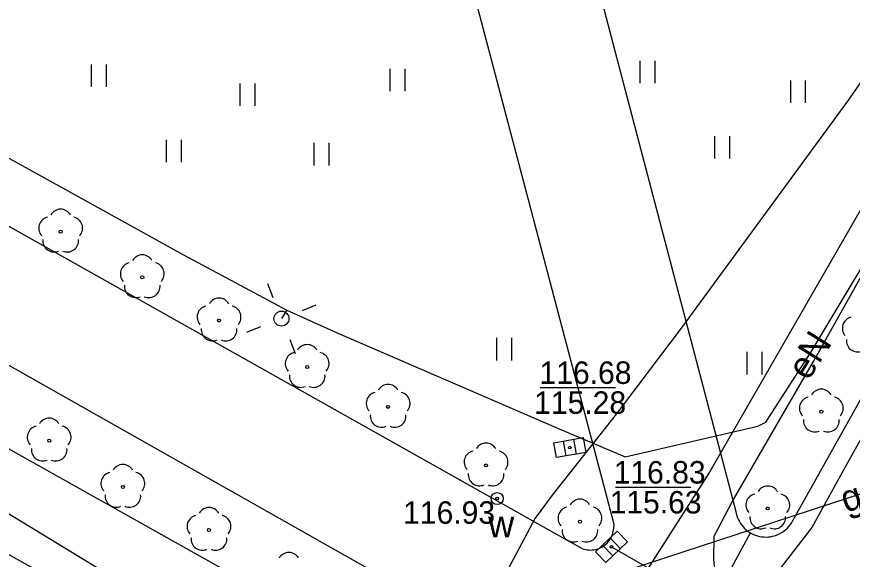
# Model space of a CAD drawing. Extents: x 6434771 to 6436222, y 5663454 to 5664782.
# Drawn here: x 6435389.91 to 6435417.79, y 5663841.05 to 5663859.17 of the extents above; entities that cross this region are included whole.
import ezdxf

# ---------------------------------------------------------------- set-up
doc = ezdxf.new("R2010")
doc.units = 0
for name, color, linetype in [('Warstwa 10', 7, 'Continuous'), ('Warstwa 11', 7, 'Continuous'), ('Warstwa 12', 7, 'Continuous'), ('Warstwa 13', 7, 'Continuous'), ('Warstwa 14', 7, 'Continuous'), ('Warstwa 2', 7, 'Continuous'), ('Warstwa 4', 7, 'Continuous'), ('Warstwa 5', 7, 'Continuous'), ('Warstwa 6', 7, 'Continuous'), ('Warstwa 7', 7, 'Continuous'), ('Warstwa 8', 7, 'Continuous')]:
    doc.layers.add(name, color=color, linetype=linetype)

msp = doc.modelspace()

# ---------------------------------------------------------------- linework, layer by layer
at = {"layer": 'Warstwa 10'}
for points in [[(6435463.66, 5663935.12), (6435460.91, 5663924.89), (6435462.44, 5663921.82), (6435441.07, 5663889.25), (6435439.33, 5663885.38), (6435437.4, 5663886.34), (6435413.02, 5663843.96), (6435405.83, 5663832.69), (6435402.55, 5663834.24), (6435396.16, 5663837.88), (6435373.33, 5663794.86)], [(6435335.178, 5663890.938), (6435338.107, 5663876.762), (6435339.024, 5663872.265), (6435340.015, 5663871.796), (6435342.311, 5663870.369), (6435348.64, 5663866.658), (6435357.869, 5663861.307), (6435368.081, 5663855.303), (6435372.357, 5663852.748), (6435378.044, 5663849.395), (6435386.974, 5663844.189), (6435394.104, 5663839.85), (6435398.635, 5663837.219), (6435400.345, 5663836.282), (6435405.663, 5663833.365), (6435414.229, 5663828.613), (6435413.94, 5663822.627), (6435413.836, 5663820.771), (6435413.916, 5663820.663), (6435415.865, 5663819.454), (6435420.004, 5663817.009), (6435420.232, 5663816.158), (6435417.642, 5663813.363)]]:
    msp.add_lwpolyline(points, dxfattribs=at)
at = {"layer": 'Warstwa 11'}
for centre in [(6435391.373, 5663851.992), (6435394.096, 5663850.467), (6435396.658, 5663849.023), (6435399.599, 5663847.471), (6435402.3, 5663846.14), (6435416.753, 5663845.981), (6435390.99, 5663845.012), (6435405.567, 5663844.183), (6435393.449, 5663843.466), (6435414.966, 5663842.748), (6435408.699, 5663842.307), (6435396.322, 5663842.03)]:
    msp.add_circle(centre, 0.05, dxfattribs=at)
for centre, start, end in [((6435391.373, 5663852.367), 30.1471, 149.8529), ((6435391.016, 5663852.108), 102.1471, 221.8529), ((6435391.73, 5663852.108), 318.1471, 77.8529), ((6435391.153, 5663851.689), 174.1471, 293.8529), ((6435391.593, 5663851.689), 246.1471, 5.8529), ((6435394.096, 5663850.842), 30.1471, 149.8529), ((6435393.739, 5663850.583), 102.1471, 221.8529), ((6435394.453, 5663850.583), 318.1471, 77.8529), ((6435393.876, 5663850.164), 174.1471, 293.8529), ((6435394.316, 5663850.164), 246.1471, 5.8529), ((6435396.658, 5663849.398), 30.1471, 149.8529), ((6435396.301, 5663849.139), 102.1471, 221.8529), ((6435397.015, 5663849.139), 318.1471, 77.8529), ((6435417.829, 5663848.77), 102.1471, 221.8529), ((6435396.438, 5663848.72), 174.1471, 293.8529), ((6435396.878, 5663848.72), 246.1471, 5.8529), ((6435399.599, 5663847.846), 30.1471, 149.8529), ((6435417.966, 5663848.351), 174.1471, 293.8529), ((6435399.242, 5663847.587), 102.1471, 221.8529), ((6435399.956, 5663847.587), 318.1471, 77.8529), ((6435399.379, 5663847.168), 174.1471, 293.8529), ((6435399.819, 5663847.168), 246.1471, 5.8529), ((6435402.3, 5663846.515), 30.1471, 149.8529), ((6435416.753, 5663846.356), 30.1471, 149.8529), ((6435401.943, 5663846.256), 102.1471, 221.8529), ((6435402.657, 5663846.256), 318.1471, 77.8529), ((6435416.396, 5663846.097), 102.1471, 221.8529), ((6435417.11, 5663846.097), 318.1471, 77.8529), ((6435390.99, 5663845.387), 30.1471, 149.8529), ((6435402.08, 5663845.837), 174.1471, 293.8529), ((6435402.52, 5663845.837), 246.1471, 5.8529), ((6435416.533, 5663845.678), 174.1471, 293.8529), ((6435416.973, 5663845.678), 246.1471, 5.8529), ((6435390.633, 5663845.128), 102.1471, 221.8529), ((6435391.347, 5663845.128), 318.1471, 77.8529), ((6435405.567, 5663844.558), 30.1471, 149.8529), ((6435390.77, 5663844.709), 174.1471, 293.8529), ((6435391.21, 5663844.709), 246.1471, 5.8529), ((6435405.21, 5663844.299), 102.1471, 221.8529), ((6435405.924, 5663844.299), 318.1471, 77.8529), ((6435393.449, 5663843.841), 30.1471, 149.8529), ((6435393.092, 5663843.582), 102.1471, 221.8529), ((6435393.806, 5663843.582), 318.1471, 77.8529), ((6435405.347, 5663843.88), 174.1471, 293.8529), ((6435405.787, 5663843.88), 246.1471, 5.8529), ((6435414.966, 5663843.123), 30.1471, 149.8529), ((6435393.229, 5663843.163), 174.1471, 293.8529), ((6435393.669, 5663843.163), 246.1471, 5.8529), ((6435414.609, 5663842.864), 102.1471, 221.8529), ((6435415.323, 5663842.864), 318.1471, 77.8529), ((6435408.699, 5663842.682), 30.1471, 149.8529), ((6435396.322, 5663842.405), 30.1471, 149.8529), ((6435408.342, 5663842.423), 102.1471, 221.8529), ((6435409.056, 5663842.423), 318.1471, 77.8529), ((6435395.965, 5663842.146), 102.1471, 221.8529), ((6435396.679, 5663842.146), 318.1471, 77.8529), ((6435414.746, 5663842.445), 174.1471, 293.8529), ((6435415.186, 5663842.445), 246.1471, 5.8529), ((6435408.479, 5663842.004), 174.1471, 293.8529), ((6435408.919, 5663842.004), 246.1471, 5.8529), ((6435396.102, 5663841.727), 174.1471, 293.8529), ((6435396.542, 5663841.727), 246.1471, 5.8529), ((6435398.987, 5663840.902), 30.1471, 149.8529)]:
    msp.add_arc(centre, 0.375, start, end, dxfattribs=at)
at = {"layer": 'Warstwa 12'}
for points in [[(6435397.393, 5663818.634), (6435398.405, 5663820.277), (6435406.531, 5663834.152), (6435410.27, 5663840.689), (6435424.375, 5663845.312), (6435429.384, 5663846.962), (6435433.786, 5663848.481), (6435435.161, 5663850.8), (6435441.745, 5663862.426), (6435445.915, 5663869.907), (6435449.367, 5663875.506), (6435454.395, 5663883.869), (6435458.364, 5663890.579), (6435460.329, 5663894.152), (6435463.858, 5663901.034), (6435468.538, 5663910.285), (6435471.476, 5663916.034), (6435475.414, 5663922.553), (6435478.498, 5663927.854), (6435482.409, 5663934.511), (6435486.541, 5663941.544)], [(6435447.062, 5663897.437), (6435443.056, 5663889.484), (6435440.358, 5663884.774), (6435435.725, 5663876.52), (6435427.878, 5663862.597), (6435426.954, 5663861.084), (6435424.544, 5663856.758), (6435421.398, 5663851.004), (6435417.624, 5663844.276), (6435416.437, 5663842.113), (6435414.485, 5663839.596), (6435412.652, 5663837.31), (6435409.926, 5663833.859), (6435408.748, 5663832.349), (6435406.751, 5663829.143), (6435405.207, 5663826.749), (6435403.608, 5663824.07), (6435401.471, 5663820.734)], [(6435441.334, 5663891.172), (6435440.258, 5663890.739), (6435440.059, 5663890.088), (6435438.9, 5663888.38), (6435435.762, 5663883.429), (6435427.511, 5663870.737), (6435422.658, 5663863.563), (6435417.63, 5663856.346), (6435412.108, 5663848.819), (6435409.908, 5663845.901), (6435407.773, 5663843.191), (6435407.208, 5663842.42), (6435406.1, 5663840.35), (6435403.6, 5663835.547), (6435399.205, 5663827.094), (6435396.22, 5663821.213), (6435395.68, 5663820.22), (6435394.576, 5663820.761), (6435385.104, 5663826.398), (6435376.487, 5663831.524), (6435367.816, 5663836.677), (6435362.451, 5663839.79), (6435354.317, 5663844.248)], [(6435432.954, 5663828.262), (6435430.584, 5663829.707), (6435425.511, 5663832.518), (6435418.442, 5663836.509), (6435414.692, 5663838.526), (6435414.003, 5663838.98), (6435413.541, 5663839.707), (6435413.243, 5663840.405), (6435413.168, 5663841.045), (6435413.178, 5663841.822), (6435413.773, 5663842.972), (6435416.493, 5663847.66), (6435422.304, 5663858.046), (6435429.673, 5663871.325), (6435437.807, 5663885.787), (6435441.334, 5663891.172)], [(6435371.655, 5663864.561), (6435374.135, 5663863.935), (6435374.75, 5663863.584), (6435375.093, 5663863.414), (6435375.656, 5663863.366), (6435376.838, 5663863.076), (6435377.353, 5663862.408), (6435378.722, 5663860.614), (6435381.246, 5663859.181), (6435383.311, 5663857.888), (6435387.683, 5663855.526), (6435395.472, 5663851.22), (6435398.917, 5663849.374), (6435400.602, 5663848.61), (6435407.924, 5663845.437), (6435410.212, 5663844.473), (6435414.638, 5663845.493), (6435414.902, 5663845.627), (6435416.417, 5663847.98), (6435421.025, 5663855.686)], [(6435398.917, 5663849.374), (6435398.739, 5663849.087)]]:
    msp.add_lwpolyline(points, dxfattribs=at)
at = {"layer": 'Warstwa 14'}
for p, q in [((6435407.372, 5663846.783), (6435409.89, 5663846.783)), ((6435409.887, 5663843.455), (6435412.4, 5663843.455))]:
    msp.add_line(p, q, dxfattribs=at)
for centre in [(6435408.36, 5663844.78), (6435409.748, 5663841.465)]:
    msp.add_circle(centre, 0.045, dxfattribs=at)
at = {"layer": 'Warstwa 2'}
msp.add_circle((6435398.739, 5663849.087), 0.25, dxfattribs=at)
at = {"layer": 'Warstwa 4'}
for p, q in [((6435408.488, 5663845.057), (6435408.576, 5663844.565)), ((6435408.144, 5663844.995), (6435408.232, 5663844.503)), ((6435409.702, 5663841.767), (6435410.047, 5663841.405)), ((6435409.449, 5663841.525), (6435409.794, 5663841.163))]:
    msp.add_line(p, q, dxfattribs=at)
for points in [[(6435398.464, 5663849.785), (6435398.28, 5663850.25)], [(6435399.437, 5663849.362), (6435399.902, 5663849.546)], [(6435398.041, 5663848.812), (6435397.576, 5663848.628)], [(6435399.014, 5663848.389), (6435399.198, 5663847.924)]]:
    msp.add_lwpolyline(points, dxfattribs=at)
for points in [[(6435407.824, 5663844.939), (6435408.808, 5663845.114), (6435408.896, 5663844.621), (6435407.912, 5663844.446)], [(6435409.214, 5663841.301), (6435409.938, 5663841.991), (6435410.282, 5663841.629), (6435409.558, 5663840.939)]]:
    msp.add_lwpolyline(points, close=True, dxfattribs=at)
msp.add_circle((6435405.937, 5663843.08), 0.2, dxfattribs=at)
at = {"layer": 'Warstwa 5'}
for p, q in [((6435415.789, 5663842.322), (6435442.58, 5663890.242)), ((6435406.321, 5663871.508), (6435413.903, 5663842.645)), ((6435402.186, 5663871.198), (6435409.808, 5663842.314)), ((6435362.09, 5663867.682), (6435408.171, 5663841.744)), ((6435356.354, 5663859.8), (6435403.411, 5663833.521)), ((6435410.708, 5663856.951), (6435410.708, 5663857.701)), ((6435411.208, 5663856.951), (6435411.208, 5663857.701)), ((6435392.407, 5663856.827), (6435392.407, 5663857.577)), ((6435392.907, 5663856.827), (6435392.907, 5663857.577)), ((6435402.369, 5663856.684), (6435402.369, 5663857.434)), ((6435402.869, 5663856.684), (6435402.869, 5663857.434)), ((6435415.73, 5663856.294), (6435415.73, 5663857.044)), ((6435416.23, 5663856.294), (6435416.23, 5663857.044)), ((6435397.361, 5663856.194), (6435397.361, 5663856.944)), ((6435397.861, 5663856.194), (6435397.861, 5663856.944)), ((6435413.203, 5663854.437), (6435413.203, 5663855.187)), ((6435413.703, 5663854.437), (6435413.703, 5663855.187)), ((6435394.901, 5663854.313), (6435394.901, 5663855.063)), ((6435395.401, 5663854.313), (6435395.401, 5663855.063)), ((6435399.836, 5663854.207), (6435399.836, 5663854.957)), ((6435400.336, 5663854.207), (6435400.336, 5663854.957)), ((6435405.922, 5663847.695), (6435405.922, 5663848.445)), ((6435406.422, 5663847.695), (6435406.422, 5663848.445)), ((6435414.277, 5663847.226), (6435414.277, 5663847.976)), ((6435414.777, 5663847.226), (6435414.777, 5663847.976)), ((6435413.903, 5663842.645), (6435413.917, 5663842.575)), ((6435413.917, 5663842.575), (6435413.936, 5663842.505)), ((6435409.808, 5663842.314), (6435409.819, 5663842.259)), ((6435409.819, 5663842.259), (6435409.825, 5663842.204)), ((6435413.936, 5663842.505), (6435413.959, 5663842.438)), ((6435413.959, 5663842.438), (6435413.988, 5663842.372)), ((6435413.988, 5663842.372), (6435414.021, 5663842.308)), ((6435414.021, 5663842.308), (6435414.058, 5663842.247)), ((6435415.712, 5663842.201), (6435415.753, 5663842.26)), ((6435415.753, 5663842.26), (6435415.789, 5663842.322)), ((6435409.798, 5663841.927), (6435409.812, 5663841.981)), ((6435409.812, 5663841.981), (6435409.821, 5663842.036)), ((6435409.821, 5663842.036), (6435409.826, 5663842.092)), ((6435409.825, 5663842.204), (6435409.828, 5663842.148)), ((6435409.826, 5663842.092), (6435409.828, 5663842.148)), ((6435414.058, 5663842.247), (6435414.1, 5663842.188)), ((6435414.1, 5663842.188), (6435414.145, 5663842.133)), ((6435414.145, 5663842.133), (6435414.195, 5663842.081)), ((6435414.195, 5663842.081), (6435414.248, 5663842.032)), ((6435414.248, 5663842.032), (6435414.304, 5663841.988)), ((6435414.304, 5663841.988), (6435414.364, 5663841.948)), ((6435415.452, 5663841.956), (6435415.511, 5663841.998)), ((6435415.511, 5663841.998), (6435415.566, 5663842.043)), ((6435415.566, 5663842.043), (6435415.619, 5663842.092)), ((6435415.619, 5663842.092), (6435415.667, 5663842.145)), ((6435415.667, 5663842.145), (6435415.712, 5663842.201)), ((6435408.171, 5663841.744), (6435408.777, 5663841.407)), ((6435409.676, 5663841.677), (6435409.707, 5663841.723)), ((6435409.707, 5663841.723), (6435409.736, 5663841.772)), ((6435409.736, 5663841.772), (6435409.76, 5663841.822)), ((6435409.76, 5663841.822), (6435409.781, 5663841.874)), ((6435409.781, 5663841.874), (6435409.798, 5663841.927)), ((6435414.364, 5663841.948), (6435414.395, 5663841.93)), ((6435414.395, 5663841.93), (6435414.426, 5663841.912)), ((6435414.426, 5663841.912), (6435414.491, 5663841.88)), ((6435414.491, 5663841.88), (6435414.557, 5663841.853)), ((6435414.557, 5663841.853), (6435414.625, 5663841.831)), ((6435414.625, 5663841.831), (6435414.695, 5663841.814)), ((6435414.695, 5663841.814), (6435414.766, 5663841.802)), ((6435414.766, 5663841.802), (6435414.837, 5663841.795)), ((6435414.837, 5663841.795), (6435414.909, 5663841.793)), ((6435414.909, 5663841.793), (6435414.981, 5663841.796)), ((6435414.981, 5663841.796), (6435415.052, 5663841.804)), ((6435415.052, 5663841.804), (6435415.123, 5663841.818)), ((6435415.123, 5663841.818), (6435415.192, 5663841.836)), ((6435415.192, 5663841.836), (6435415.26, 5663841.859)), ((6435415.26, 5663841.859), (6435415.326, 5663841.887)), ((6435415.326, 5663841.887), (6435415.39, 5663841.919)), ((6435415.39, 5663841.919), (6435415.452, 5663841.956)), ((6435409.325, 5663841.41), (6435409.376, 5663841.432)), ((6435409.376, 5663841.432), (6435409.426, 5663841.457)), ((6435409.426, 5663841.457), (6435409.474, 5663841.486)), ((6435409.474, 5663841.486), (6435409.52, 5663841.518)), ((6435409.52, 5663841.518), (6435409.563, 5663841.554)), ((6435409.563, 5663841.554), (6435409.603, 5663841.592)), ((6435409.603, 5663841.592), (6435409.641, 5663841.633)), ((6435409.641, 5663841.633), (6435409.676, 5663841.677)), ((6435408.777, 5663841.407), (6435408.83, 5663841.39)), ((6435408.83, 5663841.39), (6435408.885, 5663841.376)), ((6435408.885, 5663841.376), (6435408.94, 5663841.366)), ((6435408.94, 5663841.366), (6435408.995, 5663841.361)), ((6435408.995, 5663841.361), (6435409.051, 5663841.359)), ((6435409.051, 5663841.359), (6435409.107, 5663841.361)), ((6435409.107, 5663841.361), (6435409.163, 5663841.368)), ((6435409.163, 5663841.368), (6435409.218, 5663841.378)), ((6435409.218, 5663841.378), (6435409.272, 5663841.392)), ((6435409.272, 5663841.392), (6435409.325, 5663841.41))]:
    msp.add_line(p, q, dxfattribs=at)
at = {"layer": 'Warstwa 6'}
for centre in [(6435408.36, 5663844.78), (6435405.937, 5663843.08), (6435409.748, 5663841.465)]:
    msp.add_circle(centre, 0.045, dxfattribs=at)
at = {"layer": 'Warstwa 7'}
msp.add_lwpolyline([(6435409.748, 5663841.465), (6435419.602, 5663835.801)], dxfattribs=at)
at = {"layer": 'Warstwa 8'}
for p, q in [((6435415.789, 5663842.322), (6435442.58, 5663890.242)), ((6435406.321, 5663871.508), (6435413.903, 5663842.645)), ((6435402.186, 5663871.198), (6435409.808, 5663842.314)), ((6435362.09, 5663867.682), (6435408.171, 5663841.744)), ((6435360.367, 5663864.122), (6435406.416, 5663838.025)), ((6435359.318, 5663861.735), (6435404.735, 5663836.275)), ((6435356.354, 5663859.8), (6435403.411, 5663833.521)), ((6435413.903, 5663842.645), (6435413.917, 5663842.575)), ((6435413.917, 5663842.575), (6435413.936, 5663842.505)), ((6435409.808, 5663842.314), (6435409.819, 5663842.259)), ((6435409.819, 5663842.259), (6435409.825, 5663842.204)), ((6435413.936, 5663842.505), (6435413.959, 5663842.438)), ((6435413.959, 5663842.438), (6435413.988, 5663842.372)), ((6435413.988, 5663842.372), (6435414.021, 5663842.308)), ((6435414.021, 5663842.308), (6435414.058, 5663842.247)), ((6435415.712, 5663842.201), (6435415.753, 5663842.26)), ((6435415.753, 5663842.26), (6435415.789, 5663842.322)), ((6435409.798, 5663841.927), (6435409.812, 5663841.981)), ((6435409.812, 5663841.981), (6435409.821, 5663842.036)), ((6435409.821, 5663842.036), (6435409.826, 5663842.092)), ((6435409.825, 5663842.204), (6435409.828, 5663842.148)), ((6435409.826, 5663842.092), (6435409.828, 5663842.148)), ((6435414.058, 5663842.247), (6435414.1, 5663842.188)), ((6435414.1, 5663842.188), (6435414.145, 5663842.133)), ((6435414.145, 5663842.133), (6435414.195, 5663842.081)), ((6435414.195, 5663842.081), (6435414.248, 5663842.032)), ((6435414.248, 5663842.032), (6435414.304, 5663841.988)), ((6435414.304, 5663841.988), (6435414.364, 5663841.948)), ((6435415.452, 5663841.956), (6435415.511, 5663841.998)), ((6435415.511, 5663841.998), (6435415.566, 5663842.043)), ((6435415.566, 5663842.043), (6435415.619, 5663842.092)), ((6435415.619, 5663842.092), (6435415.667, 5663842.145)), ((6435415.667, 5663842.145), (6435415.712, 5663842.201)), ((6435408.171, 5663841.744), (6435408.777, 5663841.407)), ((6435408.603, 5663831.392), (6435414.395, 5663841.93)), ((6435408.603, 5663831.392), (6435414.395, 5663841.93)), ((6435409.676, 5663841.677), (6435409.707, 5663841.723)), ((6435409.707, 5663841.723), (6435409.736, 5663841.772)), ((6435409.736, 5663841.772), (6435409.76, 5663841.822)), ((6435409.76, 5663841.822), (6435409.781, 5663841.874)), ((6435409.781, 5663841.874), (6435409.798, 5663841.927)), ((6435414.364, 5663841.948), (6435414.395, 5663841.93)), ((6435414.395, 5663841.93), (6435414.426, 5663841.912)), ((6435414.426, 5663841.912), (6435414.491, 5663841.88)), ((6435414.491, 5663841.88), (6435414.557, 5663841.853)), ((6435414.557, 5663841.853), (6435414.625, 5663841.831)), ((6435414.625, 5663841.831), (6435414.695, 5663841.814)), ((6435414.695, 5663841.814), (6435414.766, 5663841.802)), ((6435414.766, 5663841.802), (6435414.837, 5663841.795)), ((6435414.837, 5663841.795), (6435414.909, 5663841.793)), ((6435414.909, 5663841.793), (6435414.981, 5663841.796)), ((6435414.981, 5663841.796), (6435415.052, 5663841.804)), ((6435415.052, 5663841.804), (6435415.123, 5663841.818)), ((6435415.123, 5663841.818), (6435415.192, 5663841.836)), ((6435415.192, 5663841.836), (6435415.26, 5663841.859)), ((6435415.26, 5663841.859), (6435415.326, 5663841.887)), ((6435415.326, 5663841.887), (6435415.39, 5663841.919)), ((6435415.39, 5663841.919), (6435415.452, 5663841.956)), ((6435409.325, 5663841.41), (6435409.376, 5663841.432)), ((6435409.376, 5663841.432), (6435409.426, 5663841.457)), ((6435409.426, 5663841.457), (6435409.474, 5663841.486)), ((6435409.474, 5663841.486), (6435409.52, 5663841.518)), ((6435409.52, 5663841.518), (6435409.563, 5663841.554)), ((6435409.563, 5663841.554), (6435409.603, 5663841.592)), ((6435409.603, 5663841.592), (6435409.641, 5663841.633)), ((6435409.641, 5663841.633), (6435409.676, 5663841.677)), ((6435408.777, 5663841.407), (6435408.83, 5663841.39)), ((6435408.83, 5663841.39), (6435408.885, 5663841.376)), ((6435408.885, 5663841.376), (6435408.94, 5663841.366)), ((6435408.94, 5663841.366), (6435408.995, 5663841.361)), ((6435408.995, 5663841.361), (6435409.051, 5663841.359)), ((6435409.051, 5663841.359), (6435409.107, 5663841.361)), ((6435409.107, 5663841.361), (6435409.163, 5663841.368)), ((6435409.163, 5663841.368), (6435409.218, 5663841.378)), ((6435409.218, 5663841.378), (6435409.272, 5663841.392)), ((6435409.272, 5663841.392), (6435409.325, 5663841.41))]:
    msp.add_line(p, q, dxfattribs=at)

# ---------------------------------------------------------------- texts
at = {"layer": 'Warstwa 13'}
for s, rotation, p in [('eN', 57.9031, (6435416.319, 5663846.983)), ('gA100', 18.8389, (6435417.576, 5663842.593))]:
    msp.add_text(s, height=0.9, rotation=rotation, dxfattribs=at).set_placement(p)
at = {"layer": 'Warstwa 14'}
for s, p in [('115.28', (6435407.173, 5663845.908)), ('115.63', (6435409.689, 5663842.58))]:
    msp.add_text(s, height=0.75, dxfattribs=at).set_placement(p)
at = {"layer": 'Warstwa 5'}
msp.add_text('w', height=0.9, dxfattribs=at).set_placement((6435405.637, 5663841.781))
at = {"layer": 'Warstwa 6'}
for s, p in [('116.68', (6435407.351, 5663846.908)), ('116.83', (6435409.823, 5663843.58)), ('116.93', (6435402.8, 5663842.237))]:
    msp.add_text(s, height=0.75, dxfattribs=at).set_placement(p)

doc.saveas('drawing.dxf')
